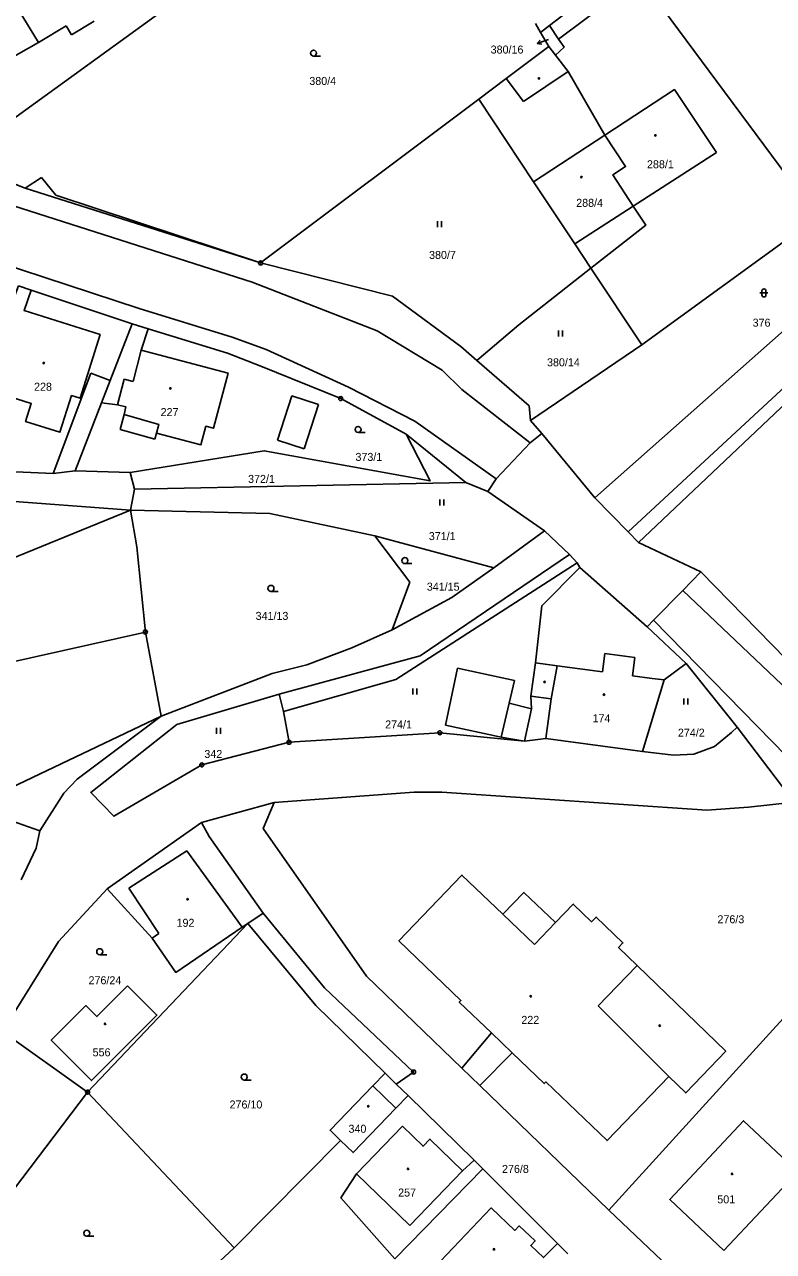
# Model space of a CAD drawing. Extents: x -745926 to -742978, y -968282 to -965689.
# Drawn here: x -744718.8 to -744625.3, y -966751.7 to -966598.4 of the extents above; entities that cross this region are included whole.
import ezdxf

# ---------------------------------------------------------------- set-up
doc = ezdxf.new("R2010")
doc.units = 0
for name, color, linetype in [('Hranice parcel', 7, 'Continuous'), ('Parcelní čísla', 7, 'Continuous'), ('Pop  PČ popisy', 7, 'Continuous'), ('Vnitřní kresba', 7, 'Continuous'), ('Značky bodu BP', 7, 'Continuous'), ('Značky budov', 7, 'Continuous'), ('Značky kultur', 7, 'Continuous')]:
    doc.layers.add(name, color=color, linetype=linetype)

msp = doc.modelspace()

# ---------------------------------------------------------------- linework, layer by layer
at = {"layer": 'Hranice parcel'}
for p, q in [((-744727.43, -966615.48), (-744701.27, -966596.5)), ((-744654.98, -966598.3), (-744654.34, -966599.41)), ((-744654.34, -966599.41), (-744653.23, -966598.56)), ((-744653.32, -966601.18), (-744654.34, -966599.41)), ((-744653.23, -966598.56), (-744652.09, -966600.26)), ((-744652.5, -966602.25), (-744653.32, -966601.18)), ((-744689.3, -966628.22), (-744662.06, -966607.75)), ((-744655.22, -966618.08), (-744662.06, -966607.75)), ((-744619.79, -966622.48), (-744641.7, -966638.46)), ((-744648.06, -966628.88), (-744641.7, -966638.46)), ((-744717.95, -966631.6), (-744719.52, -966631.07)), ((-744705.35, -966635.83), (-744717.95, -966631.6)), ((-744703.35, -966636.44), (-744705.35, -966635.83)), ((-744641.7, -966638.46), (-744655.62, -966647.91)), ((-744709.18, -966645.69), (-744712.48, -966654.2)), ((-744663.66, -966655.63), (-744671.15, -966649.6)), ((-744705.6, -966654.39), (-744712.48, -966654.2)), ((-744705.05, -966656.48), (-744705.6, -966654.39)), ((-744663.66, -966655.63), (-744705.05, -966656.48)), ((-744705.54, -966659.11), (-744730.81, -966657.23)), ((-744705.05, -966656.48), (-744705.54, -966659.11)), ((-744647.58, -966657.55), (-744643.39, -966661.79)), ((-744670.68, -966668.08), (-744675.06, -966662.3)), ((-744660.19, -966666.29), (-744675.06, -966662.3)), ((-744660.19, -966666.29), (-744653.84, -966661.68)), ((-744650.73, -966664.66), (-744653.84, -966661.68)), ((-744643.39, -966661.79), (-744642.11, -966663.14)), ((-744649.78, -966665.7), (-744650.73, -966664.66)), ((-744649.46, -966666.27), (-744649.78, -966665.7)), ((-744672.87, -966674.07), (-744670.68, -966668.08)), ((-744701.74, -966684.82), (-744703.69, -966674.33)), ((-744629.78, -966686.2), (-744636.15, -966678.25)), ((-744725.41, -966696.15), (-744701.74, -966684.82)), ((-744686.45, -966684.25), (-744685.75, -966688.1)), ((-744622.7, -966695.6), (-744629.78, -966686.2)), ((-744687.63, -966695.61), (-744696.68, -966698.13)), ((-744696.68, -966698.13), (-744708.45, -966706.39)), ((-744690.9, -966710.75), (-744710.9, -966731.8)), ((-744710.9, -966731.8), (-744721.55, -966724.25)), ((-744664.18, -966728.82), (-744661.95, -966730.97)), ((-744661.95, -966730.97), (-744645.84, -966746.54)), ((-744733.65, -966761.72), (-744710.9, -966731.8)), ((-744710.9, -966731.8), (-744692.6, -966751.25)), ((-744670.9, -966732.24), (-744662.65, -966740.31)), ((-744692.6, -966751.25), (-744679.33, -966737.83)), ((-744661.55, -966741.39), (-744662.65, -966740.31)), ((-744672.56, -966752.63), (-744661.55, -966741.39)), ((-744661.55, -966741.39), (-744652.22, -966750.73)), ((-744645.84, -966746.54), (-744631.18, -966760.42)), ((-744692.6, -966751.25), (-744718.03, -966774.76)), ((-744650.95, -966752), (-744652.22, -966750.73))]:
    msp.add_line(p, q, dxfattribs=at)
for points in [[(-744701.27, -966596.5), (-744707.68, -966587.65), (-744713.09, -966580.18), (-744722.16, -966586.05), (-744728.83, -966590.26), (-744727, -966593.31), (-744722.74, -966590.77), (-744721.41, -966593.48), (-744717.03, -966600.68), (-744726.42, -966605.96), (-744727.43, -966615.48)], [(-744653.23, -966598.56), (-744633.37, -966583.31), (-744610.98, -966610.94), (-744606.23, -966614.33)], [(-744619.79, -966622.48), (-744641.9, -966592.6), (-744652.09, -966600.26)], [(-744662.06, -966607.75), (-744658.64, -966605.18), (-744653.32, -966601.18)], [(-744652.09, -966600.26), (-744651.42, -966601.27), (-744652.5, -966602.25)], [(-744652.5, -966602.25), (-744650.92, -966604.32), (-744646.32, -966612.26)], [(-744647.58, -966657.55), (-744623.94, -966636.62), (-744602.57, -966617.89), (-744590.26, -966607.1)], [(-744587.47, -966609.99), (-744599.63, -966621.25), (-744643.39, -966661.79)], [(-744586.51, -966610.56), (-744598.85, -966622.14), (-744615.78, -966638.18), (-744632.9, -966654.4), (-744639.86, -966661), (-744642.11, -966663.14)], [(-744646.32, -966612.26), (-744643.73, -966616.19), (-744645.33, -966617.23), (-744642.79, -966621.14), (-744641.21, -966623.51), (-744648.06, -966628.88)], [(-744727.43, -966615.48), (-744718.72, -966618.88), (-744689.3, -966628.22)], [(-744648.06, -966628.88), (-744650.07, -966625.85), (-744655.22, -966618.08)], [(-744689.3, -966628.22), (-744672.83, -966632.38), (-744664.3, -966638.67), (-744662.3, -966640.41)], [(-744662.3, -966640.41), (-744657.05, -966635.93), (-744648.06, -966628.88)], [(-744719.52, -966631.07), (-744721.73, -966636.96), (-744723.13, -966641.4), (-744720.95, -966642.09), (-744721.74, -966644.57), (-744717.94, -966645.77), (-744718.65, -966648.02), (-744714.36, -966649.37), (-744712.91, -966644.78), (-744711.85, -966645.12), (-744709.34, -966637.16), (-744718.84, -966634.16), (-744717.95, -966631.6)], [(-744705.35, -966635.83), (-744708.09, -966642.9), (-744709.18, -966645.69)], [(-744709.18, -966645.69), (-744707.19, -966645.93), (-744706.12, -966646.21), (-744706.33, -966647.17), (-744702.01, -966648.38), (-744702.31, -966649.48), (-744696.75, -966650.94), (-744696.14, -966648.61), (-744695.18, -966648.86), (-744693.36, -966641.97), (-744704.2, -966639.12), (-744703.35, -966636.44)], [(-744671.15, -966649.6), (-744679.3, -966645.16), (-744689.28, -966641.11), (-744693.44, -966639.49), (-744703.35, -966636.44)], [(-744662.3, -966640.41), (-744655.77, -966646.07), (-744655.62, -966647.91)], [(-744655.62, -966647.91), (-744654.18, -966649.52), (-744647.58, -966657.55)], [(-744671.15, -966649.6), (-744668.14, -966655.45), (-744688.85, -966651.67), (-744705.6, -966654.39)], [(-744712.48, -966654.2), (-744715.21, -966654.51), (-744744.18, -966653.24)], [(-744653.84, -966661.68), (-744660.94, -966656.77), (-744663.66, -966655.63)], [(-744705.54, -966659.11), (-744727.83, -966668.17), (-744734.12, -966670.73)], [(-744703.69, -966674.33), (-744704.76, -966663.68), (-744705.54, -966659.11)], [(-744675.06, -966662.3), (-744688.17, -966659.52), (-744705.54, -966659.11)], [(-744642.11, -966663.14), (-744634.33, -966666.82), (-744611.23, -966690.46)], [(-744650.73, -966664.66), (-744669.37, -966677.29), (-744687, -966682.09), (-744699.75, -966685.87), (-744710.52, -966694.38), (-744707.65, -966697.35), (-744696.65, -966690.92), (-744685.75, -966688.1)], [(-744649.78, -966665.7), (-744672.42, -966680.24), (-744686.45, -966684.25)], [(-744672.87, -966674.07), (-744665.41, -966670.03), (-744660.19, -966666.29)], [(-744649.46, -966666.27), (-744654.21, -966671.04), (-744654.99, -966678.16), (-744655.55, -966682.35), (-744655.47, -966683.92), (-744656.37, -966687.95)], [(-744636.15, -966678.25), (-744641.04, -966673.69), (-744649.46, -966666.27)], [(-744703.69, -966674.33), (-744731.26, -966680.52), (-744757.14, -966685.91)], [(-744701.74, -966684.82), (-744687.87, -966679.52), (-744683.54, -966678.42), (-744677.93, -966676.29), (-744672.87, -966674.07)], [(-744641.62, -966689.26), (-744638.9, -966680.3), (-744636.15, -966678.25)], [(-744685.75, -966688.1), (-744666.93, -966686.91), (-744656.37, -966687.95)], [(-744641.62, -966689.26), (-744637.77, -966689.73), (-744635.2, -966689.58), (-744632.64, -966688.63), (-744630.51, -966686.88), (-744629.78, -966686.2)], [(-744656.37, -966687.95), (-744653.7, -966687.64), (-744641.62, -966689.26)], [(-744622.7, -966695.6), (-744628.39, -966696.22), (-744633.6, -966696.59), (-744666.69, -966694.35), (-744670.13, -966694.33), (-744687.63, -966695.61)], [(-744719.2, -966705.27), (-744717.35, -966701.31), (-744716.86, -966699.15), (-744725.41, -966696.15)], [(-744687.63, -966695.61), (-744689, -966698.88), (-744676.08, -966717.31), (-744664.18, -966728.82)], [(-744690.9, -966710.75), (-744688.97, -966709.45), (-744695.73, -966699.89), (-744696.68, -966698.13)], [(-744661.95, -966730.97), (-744657.9, -966726.89), (-744653.89, -966730.73), (-744653.69, -966730.52), (-744646.04, -966737.86), (-744638.35, -966729.85), (-744636.22, -966731.9), (-744631.23, -966726.7), (-744642.3, -966715.97), (-744644.61, -966713.75), (-744644.06, -966713.17), (-744647.42, -966709.94), (-744647.98, -966710.52), (-744650.27, -966708.32), (-744652.49, -966710.63), (-744656.42, -966706.85), (-744659.05, -966709.59), (-744664.16, -966704.69), (-744672.04, -966712.9), (-744664.29, -966720.34), (-744664.5, -966720.55), (-744660.49, -966724.4), (-744664.18, -966728.82)], [(-744708.45, -966706.39), (-744714.53, -966713), (-744721.55, -966724.25)], [(-744708.45, -966706.39), (-744702.84, -966712.58), (-744699.9, -966716.84), (-744691.62, -966711.19), (-744690.9, -966710.75)], [(-744645.84, -966746.54), (-744612.36, -966709.73), (-744610.19, -966707.35)], [(-744690.9, -966710.75), (-744682.39, -966721), (-744673.76, -966729.44)], [(-744705.94, -966718.52), (-744702.25, -966722.17), (-744706.08, -966726.03), (-744710.42, -966730.36), (-744715.45, -966725.33), (-744711.12, -966720.99), (-744709.74, -966722.37), (-744705.94, -966718.52)], [(-744673.76, -966729.44), (-744675.29, -966731.03), (-744680.63, -966736.57), (-744679.33, -966737.83)], [(-744670.9, -966732.24), (-744672.37, -966730.8), (-744673.76, -966729.44)], [(-744679.33, -966737.83), (-744677.75, -966739.35), (-744672.41, -966733.8), (-744670.9, -966732.24)], [(-744662.65, -966740.31), (-744664.08, -966741.64), (-744668.17, -966737.68), (-744669.02, -966738.56), (-744671.59, -966736.07), (-744677.35, -966742.02), (-744679.3, -966745.02), (-744672.56, -966752.63)], [(-744631.47, -966751.61), (-744622.21, -966741.76), (-744628.99, -966735.39), (-744638.21, -966745.2), (-744631.47, -966751.61)], [(-744652.22, -966750.73), (-744654, -966752.47), (-744655.58, -966750.96), (-744655.04, -966750.39), (-744657.01, -966748.52), (-744657.56, -966749.09), (-744660.53, -966746.27), (-744669.2, -966755.41), (-744662.91, -966761.37), (-744659.15, -966757.4), (-744658.9, -966757.64), (-744657.47, -966759)]]:
    msp.add_lwpolyline(points, dxfattribs=at)
at = {"layer": 'Pop  PČ popisy'}
for p, q in [((-744653.35, -966600.31), (-744654.77, -966600.8)), ((-744654.77, -966600.8), (-744654.38, -966600.4)), ((-744654.77, -966600.8), (-744654.21, -966600.87))]:
    msp.add_line(p, q, dxfattribs=at)
at = {"layer": 'Vnitřní kresba'}
for p, q in [((-744710.1, -966598.02), (-744712.91, -966599.73)), ((-744713.6, -966598.59), (-744717.03, -966600.68)), ((-744712.91, -966599.73), (-744713.6, -966598.59)), ((-744656.47, -966608.06), (-744658.64, -966605.18)), ((-744650.92, -966604.32), (-744656.47, -966608.06)), ((-744655.22, -966618.08), (-744646.32, -966612.26)), ((-744632.4, -966614.41), (-744642.79, -966621.14)), ((-744718.72, -966618.88), (-744716.67, -966617.53)), ((-744716.67, -966617.53), (-744714.88, -966619.74)), ((-744729.2, -966618.19), (-744690.35, -966630.62)), ((-744714.88, -966619.74), (-744689.3, -966628.22)), ((-744642.79, -966621.14), (-744650.07, -966625.85)), ((-744704.46, -966633.91), (-744733.87, -966624.25)), ((-744690.35, -966630.62), (-744674.77, -966636.7)), ((-744692.87, -966637.49), (-744704.46, -966633.91)), ((-744688.63, -966639.03), (-744692.87, -966637.49)), ((-744674.77, -966636.7), (-744666.63, -966641.62)), ((-744705.23, -966643.02), (-744704.2, -966639.12)), ((-744678.33, -966643.72), (-744688.63, -966639.03)), ((-744710.5, -966641.97), (-744715.21, -966654.51)), ((-744708.09, -966642.9), (-744710.5, -966641.97)), ((-744666.63, -966641.62), (-744664.16, -966644.03)), ((-744707.19, -966645.93), (-744706.35, -966642.73)), ((-744706.35, -966642.73), (-744705.23, -966643.02)), ((-744670.03, -966648), (-744678.33, -966643.72)), ((-744664.16, -966644.03), (-744655.63, -966650.71)), ((-744687.2, -966650.35), (-744685.41, -966644.82)), ((-744685.41, -966644.82), (-744682.06, -966645.9)), ((-744706.33, -966647.17), (-744706.84, -966649.02)), ((-744682.06, -966645.9), (-744683.85, -966651.44)), ((-744659.89, -966655.17), (-744670.03, -966648)), ((-744706.84, -966649.02), (-744702.52, -966650.23)), ((-744702.52, -966650.23), (-744702.31, -966649.48)), ((-744655.63, -966650.71), (-744654.18, -966649.52)), ((-744683.85, -966651.44), (-744687.2, -966650.35)), ((-744655.63, -966650.71), (-744659.89, -966655.17)), ((-744659.89, -966655.17), (-744660.94, -966656.77)), ((-744634.33, -966666.82), (-744636.59, -966669.13)), ((-744636.59, -966669.13), (-744640.26, -966672.85)), ((-744636.59, -966669.13), (-744612.76, -966691.81)), ((-744640.26, -966672.85), (-744641.04, -966673.69)), ((-744618.94, -966694.66), (-744640.26, -966672.85)), ((-744646.62, -966679.28), (-744646.31, -966677)), ((-744646.31, -966677), (-744642.57, -966677.5)), ((-744642.57, -966677.5), (-744642.88, -966679.8)), ((-744664.73, -966678.84), (-744666.21, -966685.95)), ((-744657.6, -966680.4), (-744664.73, -966678.84)), ((-744654.99, -966678.16), (-744652.26, -966678.53)), ((-744653.04, -966682.68), (-744652.26, -966678.53)), ((-744652.26, -966678.53), (-744646.62, -966679.28)), ((-744658.27, -966683.2), (-744657.6, -966680.4)), ((-744642.88, -966679.8), (-744640.4, -966680.14)), ((-744640.4, -966680.14), (-744638.9, -966680.3)), ((-744687, -966682.09), (-744686.45, -966684.25)), ((-744653.04, -966682.68), (-744655.55, -966682.35)), ((-744659.25, -966687.45), (-744658.27, -966683.2)), ((-744655.47, -966683.92), (-744658.27, -966683.2)), ((-744653.7, -966687.64), (-744653.04, -966682.68)), ((-744712.19, -966692.69), (-744701.74, -966684.82)), ((-744666.21, -966685.95), (-744659.25, -966687.45)), ((-744659.25, -966687.45), (-744656.37, -966687.95)), ((-744713.88, -966694.44), (-744712.19, -966692.69)), ((-744716.86, -966699.15), (-744713.88, -966694.44)), ((-744705.77, -966706.32), (-744698.5, -966701.67)), ((-744698.5, -966701.67), (-744691.62, -966711.19)), ((-744702, -966712), (-744705.77, -966706.32)), ((-744688.97, -966709.45), (-744681.33, -966718.77)), ((-744655.12, -966713.37), (-744659.05, -966709.59)), ((-744652.49, -966710.63), (-744655.12, -966713.37)), ((-744702.84, -966712.58), (-744702, -966712)), ((-744647.15, -966721.02), (-744642.38, -966716.05)), ((-744642.3, -966715.97), (-744642.38, -966716.05)), ((-744681.33, -966718.77), (-744670.2, -966729.3)), ((-744638.35, -966729.85), (-744647.15, -966721.02)), ((-744657.9, -966726.89), (-744660.49, -966724.4)), ((-744670.2, -966729.3), (-744672.37, -966730.8)), ((-744673.91, -966732.36), (-744675.29, -966731.03)), ((-744672.41, -966733.8), (-744673.91, -966732.36)), ((-744670.69, -966748.46), (-744677.35, -966742.02)), ((-744664.08, -966741.64), (-744670.69, -966748.46))]:
    msp.add_line(p, q, dxfattribs=at)
msp.add_lwpolyline([(-744646.32, -966612.26), (-744637.63, -966606.57), (-744632.4, -966614.41)], dxfattribs=at)
at = {"layer": 'Značky bodu BP'}
for centre, radius in [((-744689.3, -966628.22), 0.25), ((-744689.3, -966628.22), 0.0152), ((-744679.3, -966645.16), 0.25), ((-744679.3, -966645.16), 0.0152), ((-744703.69, -966674.33), 0.25), ((-744703.69, -966674.33), 0.0152), ((-744666.93, -966686.91), 0.25), ((-744666.93, -966686.91), 0.0152), ((-744685.75, -966688.1), 0.25), ((-744685.75, -966688.1), 0.0152), ((-744696.65, -966690.92), 0.25), ((-744696.65, -966690.92), 0.0152), ((-744670.2, -966729.3), 0.25), ((-744670.2, -966729.3), 0.0152), ((-744710.9, -966731.8), 0.25), ((-744710.9, -966731.8), 0.0152)]:
    msp.add_circle(centre, radius, dxfattribs=at)
at = {"layer": 'Značky budov'}
for centre in [(-744654.56, -966605.17), (-744640, -966612.29), (-744649.24, -966617.49), (-744716.38, -966640.73), (-744700.56, -966643.9), (-744653.85, -966680.56), (-744646.43, -966682.15), (-744698.42, -966707.7), (-744655.57, -966719.83), (-744708.72, -966723.28), (-744639.47, -966723.5), (-744675.87, -966733.56), (-744670.89, -966741.4), (-744630.43, -966742.02), (-744660.16, -966751.44)]:
    msp.add_circle(centre, 0.0875, dxfattribs=at)
at = {"layer": 'Značky kultur'}
for p, q in [((-744682.7, -966602.39), (-744681.82, -966602.39)), ((-744667.21, -966623.74), (-744667.21, -966622.99)), ((-744666.7, -966623.74), (-744666.7, -966622.99)), ((-744626.71, -966631.72), (-744626.71, -966632.22)), ((-744626.21, -966632.22), (-744626.21, -966631.72)), ((-744626.96, -966631.97), (-744625.96, -966631.97)), ((-744652.11, -966637.41), (-744652.11, -966636.66)), ((-744651.6, -966637.41), (-744651.6, -966636.66)), ((-744677.13, -966649.4), (-744676.25, -966649.4)), ((-744666.91, -966658.5), (-744666.91, -966657.75)), ((-744666.41, -966658.5), (-744666.41, -966657.75)), ((-744671.29, -966665.78), (-744670.41, -966665.78)), ((-744688.01, -966669.26), (-744687.13, -966669.26)), ((-744670.28, -966682.13), (-744670.28, -966681.38)), ((-744669.78, -966682.13), (-744669.78, -966681.38)), ((-744636.45, -966683.38), (-744636.45, -966682.63)), ((-744635.95, -966683.38), (-744635.95, -966682.63)), ((-744694.82, -966687.06), (-744694.82, -966686.31)), ((-744694.32, -966687.06), (-744694.32, -966686.31)), ((-744709.39, -966714.64), (-744708.51, -966714.64)), ((-744691.35, -966730.3), (-744690.47, -966730.3)), ((-744711.01, -966749.81), (-744710.13, -966749.81))]:
    msp.add_line(p, q, dxfattribs=at)
for centre in [(-744682.7, -966602.01), (-744677.13, -966649.02), (-744671.29, -966665.4), (-744688.01, -966668.88), (-744709.39, -966714.26), (-744691.35, -966729.92), (-744711.01, -966749.43)]:
    msp.add_circle(centre, 0.375, dxfattribs=at)
for centre, start, end in [((-744626.46, -966631.72), 0, 180), ((-744626.46, -966632.22), 180, 359.9879)]:
    msp.add_arc(centre, 0.25, start, end, dxfattribs=at)

# ---------------------------------------------------------------- texts
at = {"layer": 'Parcelní čísla'}
for s, p in [('380/16', (-744660.58, -966602.06)), ('380/4', (-744683.22, -966605.98)), ('288/1', (-744641.06, -966616.39)), ('288/4', (-744649.9, -966621.21)), ('380/7', (-744668.27, -966627.72)), ('376', (-744627.87, -966636.18)), ('380/14', (-744653.54, -966641.13)), ('228', (-744717.59, -966644.18)), ('227', (-744701.79, -966647.35)), ('373/1', (-744677.46, -966652.95)), ('372/1', (-744690.87, -966655.7)), ('371/1', (-744668.3, -966662.84)), ('341/15', (-744668.55, -966669.16)), ('341/13', (-744689.93, -966672.81)), ('274/1', (-744673.75, -966686.37)), ('174', (-744647.86, -966685.6)), ('274/2', (-744637.2, -966687.4)), ('342', (-744696.33, -966690.06)), ('276/3', (-744632.26, -966710.71)), ('192', (-744699.8, -966711.15)), ('276/24', (-744710.79, -966718.33)), ('222', (-744656.75, -966723.28)), ('556', (-744710.28, -966727.33)), ('276/10', (-744693.18, -966733.85)), ('340', (-744678.33, -966736.88)), ('276/8', (-744659.16, -966741.9)), ('257', (-744672.13, -966744.85)), ('501', (-744632.28, -966745.7))]:
    msp.add_text(s, height=1, dxfattribs=at).set_placement(p)

doc.saveas('drawing.dxf')
